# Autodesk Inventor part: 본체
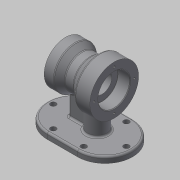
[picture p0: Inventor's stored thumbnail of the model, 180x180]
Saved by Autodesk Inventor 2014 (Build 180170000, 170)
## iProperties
Created: 2020-01
Part Number: 본체
Material: Generic
Document SubType Name: Modeling
Designer: kh
Density: 1 g/cm^3
Appearance: Default
Author: kh
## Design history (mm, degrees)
sketch "Sketch1"
  geometry: L1 (-25, 0)-(25, 0); L2 (-25, -45)-(25, -45); L3 (25, 45)-(-25, 45); A1 r 45 centre (-25, 0) between (-25, 45) and (-25, -45); A2 r 45 centre (25, 0) between (25, -45) and (25, 45); 2 further points
  constraints: 8 end point, 4 point on circle, 4 tangent, 2 centre point, 1 coincident, 1 horizontal, 1 midpoint, 1 parallel
  dimensions: "d0" = 45 radius of A1; "d1" = 50 distance of L3.start L3.end
extrude "Extrusion1" new body sketch "Sketch1" distance "d2" = 10; taper "d3" = 0 deg
sketch "Sketch2"
  geometry: L1 (-25, -45)-(25, -45) reference; L2 (25, 45)-(-25, 45) reference; L3 (25, -35)-(-25, -35); L4 (-25, 35)-(25, 35); A1 r 45 centre (25, 0) between (25, -45) and (25, 45) reference; A2 r 45 centre (-25, 0) between (-25, 45) and (-25, -45) reference; A3 r 35 centre (25, 0) between (25, -35) and (25, 35); A4 r 35 centre (-25, 0) between (-25, 35) and (-25, -35); 4 further points
  constraints: 5 point on circle, 4 end point, 2 centre point, 2 coincident, 3 other
  dimensions: "d4" = 10 distance between parallel lines of L2 L4
hole "Hole1" sketch "Sketch2" diameter "d5" = 9; stored, may be unused: countersink angle "d9" = 90 deg, drill point angle "d11" = 118 deg; dims "d6" = 6, "d7" = 4, "d8" = 2, "d10" = 8
mirror "Mirror1"
hole "Hole2" sketch "Sketch2" diameter "d12" = 9; stored, may be unused: countersink angle "d16" = 90 deg, drill point angle "d18" = 118 deg; dims "d13" = 6, "d14" = 4, "d15" = 2, "d17" = 8
mirror "Mirror2"
sketch "Sketch3"
  geometry: L1 (-40, 80)-(40, 80); L2 (70, 0)-(25, 0) reference; L3 (-70, 0)-(-70, 10) reference; L4 (-40, 80)-(-40, 120); L5 (-40, 120)-(-16, 120); L6 (-16, 120)-(-1.103, 107.5); L7 (-1.103, 107.5)-(13.289, 107.5); L8 (13.289, 107.5)-(24, 115); L9 (24, 115)-(40, 115); L10 (40, 115)-(40, 80); 1 further point
  constraints: 16 end point, 4 parallel, 1 horizontal, 1 perpendicular
  dimensions: "d19" = 80 distance from line of L2 L1.end; "d20" = 80 distance of L1.start L1.end; "d21" = 30 horizontal distance of L3.start L1.start; "d22" = 80 diameter of L5 L1; "d23" = 24 distance of L4.end L5.end; "d24" = 55 diameter of L7 L1; "d25" = 16 distance of L8.end L9.end; "d26" = 70 diameter of L9 L1; "d27" = 35 deg angle of L7 L8; "d28" = 40 deg angle of L7 L6
revolve "Revolution1" sketch "Sketch3" stored, may be unused: angle "d29" = 90 deg
sketch "Sketch4"
  geometry: L1 (25, 45)-(-25, 45) reference; L2 (70, 0)-(70, -24.272); C1 r 16 at (12, 0); A1 r 45 centre (25, 0) between (25, -45) and (25, 45) reference; A2 r 45 centre (25, 0) between (25, -45) and (25, 45) reference; 1 further point
  constraints: 2 end point, 2 tangent, 1 centre point, 1 horizontal alignment, 1 perpendicular, 1 point on circle
  dimensions: "d30" = 16 radius of C1; "d31" = 58 distance of C1.centre L2.start
extrude "Extrusion2" join sketch "Sketch4" distance "d32" = 77; taper "d33" = 0 deg
sketch "Sketch5"
  geometry: L1 (30, 45)-(30, 10); L2 (24, 45)-(40, 45) reference; L3 (70, 10)-(25, 10) reference; L4 (40, 45)-(40, 115) reference; 1 further point
  constraints: 2 end point, 2 point on line, 1 vertical
  dimensions: "d34" = 10 distance between parallel lines of L1 L4
feature "Rib1" sketch "Sketch5" dims "d35" = 1, "d36" = 10, "d37" = 0, "d38" = 0, "d39" = 1, "d40" = 1
hole "Hole3" diameter "d43" = 32; stored, may be unused: countersink angle "d47" = 90 deg, drill point angle "d49" = 118 deg; dims "d41" = 10, "d42" = 10, "d44" = 6, "d45" = 52, "d46" = 20, "d48" = 8
hole "Hole4" diameter "d52" = 40; stored, may be unused: countersink angle "d56" = 90 deg, drill point angle "d58" = 0 deg; dims "d53" = 6, "d54" = 52, "d55" = 20, "d57" = 17, "d85" = 10, "d86" = 10
sketch "Sketch7" dims "d59" = 66
  geometry: C1 r 26 at (0, 0) reference; C2 r 40 at (0, 0) reference; 3 further points
  constraints: 2 horizontal alignment, 1 coincident, 2 other
hole "Hole5" sketch "Sketch7" at (-33, 0) diameter "d60" = 3.242; stored, may be unused: countersink angle "d64" = 90 deg, drill point angle "d66" = 118 deg; dims "d61" = 9, "d62" = 52, "d63" = 20, "d65" = 11
pattern_circular "Circular Pattern1" dims angle "d68" = 360 deg
sketch "Sketch8" dims "d70" = 55
  geometry: C1 r 20 at (0, 0) reference; C2 r 35 at (0, 0) reference; 3 further points
  constraints: 2 horizontal alignment, 1 coincident, 2 other
hole "Hole6" sketch "Sketch8" at (27.5, 0) diameter "d71" = 3.242; stored, may be unused: countersink angle "d75" = 90 deg, drill point angle "d77" = 118 deg; dims "d72" = 9, "d73" = 52, "d74" = 20, "d76" = 11
pattern_circular "Circular Pattern2" dims angle "d79" = 360 deg
sketch "Sketch9"
  geometry: L1 (50, 0)-(0, 0) reference; L2 (95, 0)-(95, -10) reference; 2 further points
  constraints: 1 other
  dimensions: "d81" = 4 distance from line of L1 point (25, -4); "d82" = 70 distance from line of point (25, -4) L2
emboss "Emboss1" sketch "Sketch9" dims "d0" = 45, "d1" = 50, "d83" = 0.5, "d84" = 0
fillet "Fillet1" dims "d87" = 0.3
chamfer "Chamfer1" distance "d88" = 1; stored, may be unused: second distance "d89" = 2, angle "d90" = 45 deg
fillet "Fillet2" dims "d91" = 3
fillet "Fillet3" dims "d92" = 3
fillet "Fillet4" dims "d93" = 3
fillet "Fillet5" dims "d94" = 3
fillet "Fillet6" dims "d95" = 3
body "Solid1"
